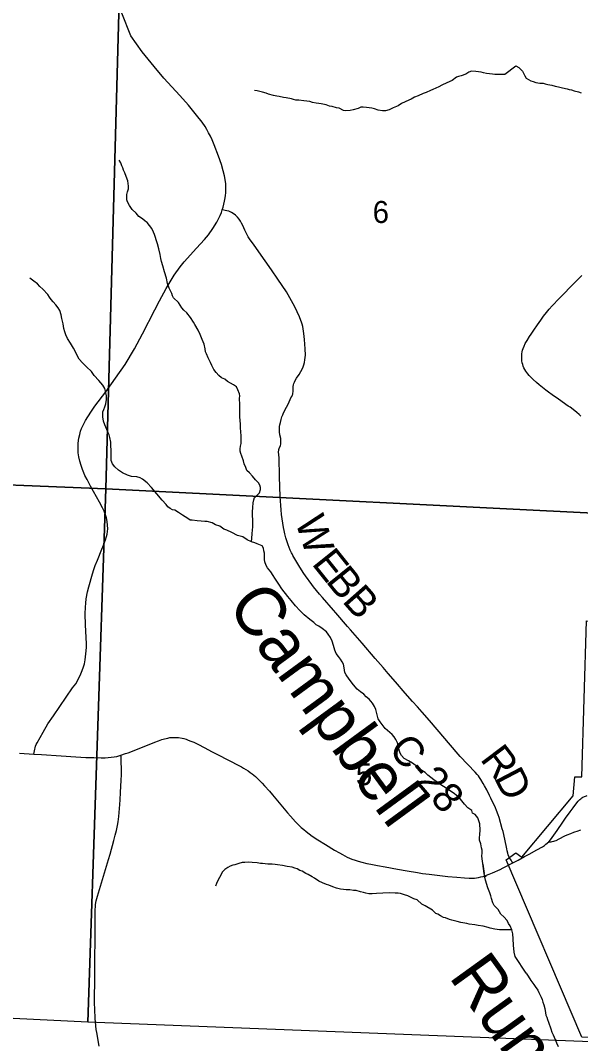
# Model space of a CAD drawing. Extents: x 0 to 34, y 0 to 22.
# Drawn here: x 4.079 to 5.147, y 17.611 to 19.561 of the extents above; entities that cross this region are included whole.
import ezdxf

# ---------------------------------------------------------------- set-up
doc = ezdxf.new("R2010")
doc.units = 0
for name, color, linetype in [('GM_X_City_Street', 7, 'Continuous'), ('GM_X_Corporation', 7, 'Continuous'), ('GM_X_County_Road', 7, 'Continuous'), ('GM_X_County_Road_Text', 7, 'Continuous'), ('GM_X_Minor_River', 7, 'Continuous'), ('GM_X_Minor_River_Text', 7, 'Continuous'), ('GM_X_Section_Text', 7, 'Continuous'), ('GM_X_State_Route', 7, 'Continuous'), ('GM_X_Township_Road', 7, 'Continuous')]:
    doc.layers.add(name, color=color, linetype=linetype)

msp = doc.modelspace()

# ---------------------------------------------------------------- linework, layer by layer
at = {"layer": 'GM_X_City_Street'}
msp.add_lwpolyline([(5.0858, 17.9954), (5.088, 17.9954), (5.0903, 17.9954), (5.0927, 17.9957), (5.0955, 17.9962), (5.0978, 17.9968), (5.0999, 17.9976), (5.1061, 18.0008), (5.1165, 18.0064), (5.1208, 18.0084), (5.128, 18.0113), (5.1338, 18.0136), (5.1418, 18.0162), (5.145, 18.0172), (5.1474, 18.0179)], dxfattribs=at)
at = {"layer": 'GM_X_Corporation'}
for points in [[(3.2518, 19.8039), (4.2724, 19.7849), (4.2417, 18.6679), (3.2101, 18.7098), (3.226, 19.805)], [(4.2853, 19.7839), (5.2933, 19.7705), (5.2887, 19.6211), (5.2602, 18.6174), (4.2417, 18.6679), (4.2724, 19.7849)], [(4.2417, 18.6679), (4.2074, 17.6513), (3.1848, 17.7013), (3.2101, 18.7098)], [(4.2417, 18.6679), (5.2602, 18.6174), (5.2318, 17.611), (4.2074, 17.6513)], [(5.1491, 17.6228), (5.0046, 17.9608), (5.023, 17.9742), (5.0344, 17.9657), (5.1325, 18.083), (5.1358, 18.119), (5.1491, 18.119), (5.158, 18.4166), (5.527, 18.415), (5.5234, 18.0969), (5.4552, 18.0962), (5.4557, 17.9574), (5.3812, 17.9572), (5.3516, 17.6218)]]:
    msp.add_lwpolyline(points, close=True, dxfattribs=at)
at = {"layer": 'GM_X_County_Road'}
for points in [[(4.1424, 18.2356), (4.1787, 18.2889), (4.1846, 18.2966), (4.1884, 18.3031), (4.1945, 18.3154), (4.197, 18.3218), (4.1993, 18.3285), (4.2011, 18.3345), (4.2026, 18.3424), (4.2047, 18.359), (4.2053, 18.3663), (4.2054, 18.3728), (4.2033, 18.4087), (4.2027, 18.4297), (4.2031, 18.4426), (4.2038, 18.4504), (4.2046, 18.4587), (4.207, 18.4717), (4.2094, 18.4815), (4.2164, 18.506), (4.219, 18.5141), (4.2217, 18.522), (4.2258, 18.5319), (4.2344, 18.5528), (4.2377, 18.5608), (4.2413, 18.5706), (4.2433, 18.5774), (4.2443, 18.5819), (4.2451, 18.587), (4.2456, 18.5921), (4.2447, 18.6061), (4.2432, 18.6127), (4.241, 18.6188), (4.2385, 18.6257), (4.2356, 18.6316), (4.2298, 18.6429), (4.2126, 18.6735), (4.2062, 18.6859), (4.2022, 18.6937), (4.1999, 18.6989), (4.1972, 18.7052), (4.1948, 18.7126), (4.1922, 18.7211), (4.1904, 18.7293), (4.1895, 18.737), (4.1891, 18.7481), (4.1893, 18.7543), (4.1899, 18.7601), (4.1907, 18.7649), (4.1922, 18.7715), (4.1939, 18.7779), (4.1958, 18.7829), (4.198, 18.788), (4.2033, 18.7985), (4.2133, 18.8145), (4.2211, 18.8259), (4.242, 18.8531), (4.2789, 18.9052), (4.2968, 18.9349), (4.3115, 18.9639), (4.3353, 19.0093), (4.3444, 19.0263), (4.357, 19.0499), (4.3724, 19.0753), (4.3837, 19.0912), (4.3913, 19.1009), (4.4144, 19.1267), (4.4301, 19.1432), (4.4378, 19.1525), (4.4457, 19.1643), (4.4532, 19.1768), (4.4596, 19.1892), (4.4623, 19.1952), (4.4639, 19.1999), (4.4654, 19.2053), (4.4667, 19.2106), (4.4681, 19.2169), (4.4691, 19.223), (4.4698, 19.2271), (4.4705, 19.2324), (4.4709, 19.237), (4.4706, 19.2498), (4.4696, 19.2579), (4.4681, 19.2652), (4.4655, 19.2747), (4.4623, 19.2864), (4.4568, 19.3026), (4.4481, 19.3243), (4.4445, 19.3334), (4.4411, 19.3406), (4.4378, 19.3471), (4.4344, 19.3534), (4.431, 19.359), (4.4252, 19.3675), (4.4149, 19.3808), (4.3994, 19.3997), (4.3828, 19.4181), (4.3526, 19.4512), (4.3341, 19.4733), (4.311, 19.5012), (4.2897, 19.5316), (4.2723, 19.5751)], [(4.5967, 18.5442), (4.5957, 18.5461), (4.5932, 18.5513), (4.5912, 18.556), (4.5891, 18.5616), (4.5872, 18.567), (4.5849, 18.5748), (4.5829, 18.5826), (4.5815, 18.5886), (4.5804, 18.5944), (4.5777, 18.6112), (4.5768, 18.619), (4.5759, 18.6284), (4.5752, 18.6365), (4.5745, 18.645), (4.5741, 18.653), (4.5731, 18.6919), (4.5721, 18.727), (4.5711, 18.7387), (4.5713, 18.7417), (4.5716, 18.7433), (4.5722, 18.745), (4.5745, 18.7509), (4.5751, 18.7532), (4.5755, 18.7557), (4.5757, 18.7579), (4.5754, 18.7621), (4.5751, 18.7644), (4.5737, 18.7713), (4.5728, 18.7769), (4.5726, 18.7796), (4.573, 18.7871), (4.5734, 18.7901), (4.5745, 18.7949), (4.5759, 18.8002), (4.5774, 18.8051), (4.579, 18.8093), (4.5807, 18.8132), (4.586, 18.8236), (4.5892, 18.8297), (4.5935, 18.8387), (4.5947, 18.8414), (4.5963, 18.8444), (4.5974, 18.8471), (4.598, 18.8486), (4.5983, 18.8502), (4.5987, 18.854), (4.5988, 18.8586), (4.5992, 18.8631), (4.5998, 18.8661), (4.6005, 18.8691), (4.6014, 18.8716), (4.6027, 18.8747), (4.6054, 18.879), (4.6102, 18.8859), (4.6137, 18.8917), (4.6164, 18.8973), (4.6179, 18.9009), (4.6191, 18.9046), (4.6202, 18.9089), (4.6211, 18.9139), (4.6218, 18.9186), (4.6223, 18.9227), (4.622, 18.9353), (4.6203, 18.9531), (4.6191, 18.9644), (4.6171, 18.9776), (4.6163, 18.9818), (4.6156, 18.9839), (4.6111, 18.9962), (4.6024, 19.0151), (4.5865, 19.0435), (4.5699, 19.0677), (4.5576, 19.0859), (4.5333, 19.1201), (4.5231, 19.1343), (4.5168, 19.1427), (4.5132, 19.1487), (4.5071, 19.161), (4.5029, 19.1705), (4.5005, 19.1747), (4.4985, 19.1782), (4.4957, 19.182), (4.4926, 19.1859), (4.4889, 19.1897), (4.4847, 19.1932), (4.4816, 19.1952), (4.479, 19.1964), (4.4761, 19.1973), (4.4728, 19.1981), (4.4639, 19.1999)], [(5.0143, 17.96), (5.0111, 17.9648), (5.0099, 17.9671), (5.0088, 17.9701), (5.0079, 17.9735), (5.007, 17.9778), (5.0061, 17.9819), (5.0024, 18.0001), (4.9989, 18.0147), (4.9973, 18.0202), (4.9912, 18.0418), (4.9897, 18.0466), (4.9864, 18.0549), (4.9843, 18.06), (4.9759, 18.0781), (4.973, 18.0836), (4.9679, 18.0942), (4.9637, 18.102), (4.9612, 18.1065), (4.9564, 18.1142), (4.9541, 18.1176), (4.952, 18.1207), (4.9495, 18.1236), (4.9456, 18.1277), (4.9173, 18.158), (4.9136, 18.1622), (4.8587, 18.2262), (4.845, 18.2421), (4.8357, 18.2522), (4.8262, 18.2628), (4.8124, 18.2788), (4.794, 18.3001), (4.7798, 18.316), (4.7705, 18.3273), (4.7553, 18.3446), (4.7303, 18.3738), (4.708, 18.399), (4.7022, 18.4059), (4.6802, 18.4316), (4.6756, 18.4368), (4.6547, 18.4609), (4.649, 18.4673), (4.6376, 18.4814), (4.6345, 18.4856), (4.6223, 18.5022), (4.6194, 18.5064), (4.6117, 18.5185), (4.6076, 18.5253), (4.5983, 18.5412), (4.5967, 18.5442)], [(4.1047, 18.1625), (4.1058, 18.1685), (4.1064, 18.1718), (4.107, 18.1746), (4.1078, 18.1776), (4.1091, 18.1805), (4.111, 18.184), (4.1223, 18.2039), (4.1317, 18.2198), (4.1424, 18.2356)], [(4.0773, 18.1639), (4.1047, 18.1625)], [(5.0176, 17.9549), (5.0158, 17.9577), (5.0143, 17.96)]]:
    msp.add_lwpolyline(points, dxfattribs=at)
at = {"layer": 'GM_X_Minor_River'}
for points in [[(5.0025, 19.4589), (5.0235, 19.4744), (5.0289, 19.4716), (5.036, 19.4646), (5.0405, 19.4553), (5.043, 19.4509), (5.0476, 19.4484), (5.0519, 19.4463), (5.0561, 19.4449), (5.0611, 19.4428), (5.0691, 19.4416), (5.0752, 19.4414), (5.0794, 19.4404), (5.0844, 19.439), (5.0916, 19.4378), (5.0982, 19.4361), (5.1043, 19.4348), (5.112, 19.4328), (5.1208, 19.4308), (5.125, 19.4295), (5.1292, 19.4288), (5.1342, 19.4267), (5.1426, 19.4248), (5.148, 19.4231)], [(5.0028, 19.4581), (4.9959, 19.4584), (4.9834, 19.4583), (4.9789, 19.459), (4.9732, 19.4593), (4.9671, 19.46), (4.9618, 19.4611), (4.9569, 19.4625), (4.9467, 19.4639), (4.9387, 19.4642), (4.9334, 19.4626), (4.9278, 19.4588), (4.9188, 19.4553), (4.9142, 19.4541), (4.9101, 19.4529), (4.9022, 19.4468), (4.8916, 19.4421), (4.8822, 19.4378), (4.8762, 19.4347), (4.8649, 19.4293), (4.8608, 19.4278), (4.8525, 19.4239), (4.8465, 19.4219), (4.8374, 19.4173), (4.8299, 19.4149), (4.8239, 19.4111), (4.8193, 19.4091), (4.8122, 19.4057), (4.8054, 19.4026), (4.7987, 19.3983), (4.7896, 19.3944), (4.7821, 19.3909), (4.7749, 19.389), (4.7692, 19.3885), (4.7609, 19.39), (4.7541, 19.3925), (4.7487, 19.3936), (4.7389, 19.3954), (4.7321, 19.3961), (4.7279, 19.3956), (4.7226, 19.3933), (4.7132, 19.3909), (4.7075, 19.3897), (4.6992, 19.3889), (4.695, 19.3896), (4.6867, 19.3937), (4.6817, 19.3947), (4.6734, 19.3969), (4.6684, 19.3976), (4.662, 19.4002), (4.6521, 19.402), (4.6476, 19.4027), (4.6426, 19.4034), (4.6358, 19.4048), (4.6309, 19.4063), (4.6195, 19.4081), (4.61, 19.4091), (4.6043, 19.4094), (4.5998, 19.4105), (4.5956, 19.4116), (4.5857, 19.4134), (4.5808, 19.4141), (4.5725, 19.4159), (4.5679, 19.4166), (4.5615, 19.418), (4.552, 19.4209), (4.5474, 19.4224), (4.5402, 19.4242), (4.5353, 19.4257), (4.5303, 19.4267), (4.5254, 19.4274)], [(4.2853, 19.2403), (4.2853, 19.2449), (4.2844, 19.2501), (4.2836, 19.2554), (4.2805, 19.2637), (4.2781, 19.2705), (4.2758, 19.2757), (4.2746, 19.2799), (4.2727, 19.284), (4.2707, 19.2897), (4.2676, 19.2945)], [(4.5196, 18.5672), (4.5206, 18.5815), (4.5216, 18.5905), (4.5223, 18.5947), (4.5221, 18.6097), (4.5216, 18.6168), (4.5216, 18.6244), (4.5218, 18.6326), (4.5225, 18.6417), (4.5239, 18.6473), (4.5254, 18.6515), (4.5295, 18.6553), (4.5347, 18.6606), (4.5369, 18.6667), (4.5365, 18.6708), (4.5357, 18.6749), (4.5326, 18.6798), (4.5273, 18.685), (4.5215, 18.6921), (4.5154, 18.6988), (4.5104, 18.7032), (4.5084, 18.7085), (4.5057, 18.7156), (4.5041, 18.7212), (4.501, 18.7306), (4.4994, 18.7358), (4.4982, 18.74), (4.4982, 18.7441), (4.4985, 18.7494), (4.4996, 18.7543), (4.4999, 18.7614), (4.4998, 18.769), (4.4993, 18.7769), (4.4988, 18.7844), (4.4984, 18.7915), (4.4974, 18.8055), (4.4974, 18.8096), (4.4976, 18.8235), (4.4972, 18.8288), (4.4967, 18.8401), (4.497, 18.8454), (4.4969, 18.8495), (4.4934, 18.857), (4.4907, 18.8626), (4.4854, 18.8663), (4.4797, 18.8693), (4.4736, 18.8726), (4.469, 18.8771), (4.4625, 18.88), (4.4575, 18.8841), (4.4522, 18.8897), (4.4479, 18.8957), (4.4441, 18.9032), (4.4413, 18.9092), (4.4371, 18.9178), (4.4336, 18.9253), (4.432, 18.9294), (4.4312, 18.9351), (4.4292, 18.9437), (4.4253, 18.9527), (4.4214, 18.9625), (4.4179, 18.9704), (4.4113, 18.9816), (4.409, 18.9857), (4.4032, 18.9951), (4.3963, 19.0037), (4.3906, 19.0089), (4.3867, 19.013), (4.3833, 19.0183), (4.3802, 19.0231), (4.371, 19.0321), (4.3687, 19.0362), (4.3675, 19.0403), (4.3628, 19.0505), (4.3597, 19.0599), (4.3573, 19.0697), (4.3538, 19.0817), (4.3506, 19.093), (4.3479, 19.1016), (4.347, 19.1073), (4.3454, 19.1152), (4.3427, 19.1257), (4.3403, 19.1355), (4.3387, 19.1412), (4.3359, 19.1491), (4.3344, 19.1532), (4.3328, 19.1577), (4.3297, 19.1645), (4.3209, 19.1757), (4.3167, 19.1783), (4.3117, 19.1832), (4.3045, 19.1876), (4.2995, 19.1936), (4.2922, 19.2007), (4.2872, 19.2082), (4.2833, 19.215), (4.2821, 19.2191), (4.2817, 19.224), (4.282, 19.2293), (4.2831, 19.2342), (4.2853, 19.2403)], [(4.1467, 19.0191), (4.1417, 19.0247), (4.1379, 19.0292), (4.1348, 19.0337), (4.1313, 19.0386), (4.1217, 19.049), (4.1164, 19.0539), (4.1114, 19.0587), (4.1049, 19.0643), (4.0973, 19.0699)], [(4.643, 18.4086), (4.638, 18.4134), (4.6304, 18.4189), (4.6201, 18.4278), (4.6116, 18.4364), (4.6036, 18.4449), (4.5951, 18.455), (4.589, 18.4628), (4.5774, 18.4777), (4.5717, 18.4866), (4.5663, 18.4937), (4.564, 18.4978), (4.5609, 18.503), (4.5562, 18.5101), (4.5501, 18.5176), (4.5474, 18.522), (4.545, 18.5288), (4.5442, 18.5333), (4.5441, 18.5453), (4.5433, 18.5502), (4.5425, 18.5547), (4.5401, 18.5595), (4.5302, 18.5632), (4.5261, 18.565), (4.5196, 18.5672), (4.5112, 18.5712), (4.5032, 18.5764), (4.4929, 18.5793), (4.4823, 18.5848), (4.4724, 18.5892), (4.4671, 18.5914), (4.459, 18.597), (4.4511, 18.5995), (4.4446, 18.6036), (4.4351, 18.6057), (4.4309, 18.6061), (4.4237, 18.6064), (4.4158, 18.6074), (4.4067, 18.6081), (4.4025, 18.6084), (4.3979, 18.6117), (4.388, 18.618), (4.3804, 18.6228), (4.3735, 18.6272), (4.369, 18.6283), (4.3648, 18.6309), (4.3598, 18.6339), (4.3571, 18.638), (4.3494, 18.6465), (4.3287, 18.6704), (4.3207, 18.6793), (4.3119, 18.6864), (4.3073, 18.689), (4.3008, 18.6908), (4.291, 18.6918), (4.2834, 18.694), (4.2739, 18.6984), (4.2659, 18.7035), (4.259, 18.7099), (4.2544, 18.7158), (4.2524, 18.7222), (4.2519, 18.7346), (4.2522, 18.7391), (4.2517, 18.7527), (4.2512, 18.7572), (4.2496, 18.7658), (4.248, 18.7711), (4.2461, 18.7752), (4.2437, 18.7812), (4.2399, 18.7902), (4.2375, 18.7973), (4.2359, 18.8052), (4.2365, 18.8147), (4.238, 18.8192), (4.2398, 18.8245), (4.242, 18.8302), (4.2431, 18.8385), (4.2434, 18.8456), (4.2414, 18.8543), (4.2402, 18.8595), (4.2359, 18.8655), (4.2283, 18.8745), (4.2198, 18.8842), (4.2148, 18.892), (4.2052, 18.9006), (4.1976, 18.9084), (4.1911, 18.9155), (4.1887, 18.9196), (4.1852, 18.9268), (4.1802, 18.9365), (4.1744, 18.9459), (4.1686, 18.9548), (4.1655, 18.962), (4.1636, 18.9672), (4.162, 18.9736), (4.1607, 18.983), (4.1584, 18.9928), (4.1571, 19), (4.154, 19.0082), (4.1513, 19.0131), (4.1467, 19.0191)], [(4.9603, 17.9526), (4.9629, 17.9346), (4.9583, 17.9676), (4.959, 17.9744), (4.959, 17.9792), (4.9581, 17.9837), (4.9565, 17.9916), (4.9542, 17.998), (4.9541, 18.0025), (4.9548, 18.0089), (4.9551, 18.0171), (4.9546, 18.0295), (4.951, 18.0408), (4.946, 18.0471), (4.9407, 18.0496), (4.9391, 18.0549), (4.9319, 18.0601), (4.9253, 18.0671), (4.9204, 18.0731), (4.9157, 18.079), (4.9062, 18.0864), (4.8921, 18.0964), (4.8787, 18.1053), (4.8669, 18.113), (4.8554, 18.1219), (4.8504, 18.1271), (4.8424, 18.1323), (4.8359, 18.1382), (4.8264, 18.1448), (4.8187, 18.1496), (4.8107, 18.154), (4.8054, 18.1596), (4.8027, 18.1641), (4.8007, 18.1697), (4.8003, 18.175), (4.7975, 18.1836), (4.7948, 18.1899), (4.7917, 18.1951), (4.7878, 18.2), (4.7787, 18.2074), (4.7745, 18.2111), (4.7702, 18.2163), (4.7648, 18.2241), (4.761, 18.2293), (4.759, 18.2372), (4.7566, 18.2473), (4.7539, 18.2529), (4.7504, 18.2592), (4.7439, 18.267), (4.7381, 18.2718), (4.7335, 18.2767), (4.7271, 18.2811), (4.7209, 18.2863), (4.7137, 18.2945), (4.7056, 18.3053), (4.6998, 18.3135), (4.6975, 18.3179), (4.697, 18.3221), (4.6962, 18.3269), (4.6946, 18.334), (4.6923, 18.3385), (4.6892, 18.3434), (4.685, 18.3486), (4.6811, 18.3542), (4.6784, 18.3605), (4.6756, 18.3695), (4.6733, 18.3777), (4.6702, 18.3845), (4.6656, 18.3908), (4.6625, 18.3956), (4.6544, 18.4019), (4.6476, 18.406), (4.643, 18.4086)], [(5.0153, 17.8273), (4.9918, 17.827), (4.9835, 17.8284), (4.9744, 17.8306), (4.9702, 17.8317), (4.9611, 17.8342), (4.9512, 17.8356), (4.9448, 17.837), (4.9345, 17.8384), (4.9296, 17.8391), (4.9224, 17.8409), (4.9182, 17.8412), (4.9114, 17.843), (4.9015, 17.8459), (4.8969, 17.847), (4.8893, 17.8499), (4.8852, 17.851), (4.8798, 17.8543), (4.8749, 17.8569), (4.8707, 17.8587), (4.8642, 17.865), (4.8504, 17.8732), (4.844, 17.8765), (4.8355, 17.8843), (4.8287, 17.8864), (4.8177, 17.892), (4.8108, 17.8938), (4.8032, 17.8963), (4.7987, 17.897), (4.793, 17.8973), (4.782, 17.8979), (4.7699, 17.8974), (4.7578, 17.8965), (4.7495, 17.8961), (4.7434, 17.896), (4.7374, 17.897), (4.7328, 17.8985), (4.7275, 17.8996), (4.7191, 17.9021), (4.7138, 17.9024), (4.707, 17.9035), (4.6998, 17.9038), (4.6949, 17.9045), (4.6892, 17.9051), (4.6812, 17.9066), (4.6748, 17.9091), (4.6671, 17.9124), (4.6626, 17.9139), (4.655, 17.9168), (4.6477, 17.9204), (4.6393, 17.926), (4.6352, 17.9282), (4.6275, 17.933), (4.623, 17.9348), (4.6161, 17.9392), (4.6119, 17.9407), (4.6066, 17.9436), (4.6024, 17.9447), (4.5967, 17.9465), (4.5872, 17.9483), (4.5789, 17.9501), (4.569, 17.9515), (4.5648, 17.9518), (4.5588, 17.9525), (4.5504, 17.9528), (4.5406, 17.9538), (4.5364, 17.9541), (4.5304, 17.9548), (4.5205, 17.9558), (4.5137, 17.9561), (4.5065, 17.956), (4.5016, 17.9556), (4.4955, 17.954), (4.488, 17.9513), (4.4839, 17.9505), (4.4786, 17.9486), (4.4741, 17.9463), (4.4688, 17.9424), (4.4636, 17.9371), (4.4617, 17.9326), (4.4584, 17.9269), (4.4554, 17.9216), (4.4528, 17.9159), (4.4506, 17.9107)], [(5.0432, 17.7449), (5.0219, 17.7762), (5.0199, 17.7845), (5.0186, 17.7984), (5.0181, 17.8104), (5.0173, 17.8198), (5.0153, 17.8273), (5.0122, 17.8351), (5.0095, 17.8396), (5.0064, 17.8452), (5.0006, 17.8519), (4.9945, 17.8575), (4.9898, 17.8661), (4.9822, 17.8739), (4.9791, 17.8788), (4.9767, 17.887), (4.9759, 17.8919), (4.9736, 17.8979), (4.97, 17.9072), (4.9653, 17.9222), (4.9641, 17.9278), (4.9629, 17.9346), (4.9629, 17.9351)], [(4.9656, 17.9297), (4.966, 17.9286)], [(5.0432, 17.7449), (5.0468, 17.739), (5.0521, 17.7309), (5.0573, 17.7232), (5.0601, 17.7192), (5.0649, 17.7122), (5.0673, 17.7077), (5.0715, 17.6988), (5.0731, 17.6944), (5.0748, 17.6895), (5.0765, 17.6843), (5.0783, 17.6772), (5.0798, 17.669), (5.0807, 17.6649), (5.082, 17.6608), (5.0836, 17.6563), (5.0854, 17.6511), (5.09, 17.6388), (5.0921, 17.6321), (5.0942, 17.6269), (5.0963, 17.6224), (5.0979, 17.6184), (5.1008, 17.6117), (5.1041, 17.6046)]]:
    msp.add_lwpolyline(points, dxfattribs=at)
at = {"layer": 'GM_X_State_Route'}
for points in [[(5.1472, 18.8066), (5.1438, 18.8101), (5.1396, 18.8138), (5.1357, 18.8169), (5.1265, 18.8237), (5.1232, 18.826), (5.1046, 18.8388), (5.0922, 18.8476), (5.0855, 18.8523), (5.0805, 18.8562), (5.0678, 18.8664), (5.0624, 18.871), (5.0565, 18.8763), (5.0528, 18.8798), (5.0489, 18.8839), (5.0462, 18.8871), (5.0426, 18.8922), (5.0404, 18.8955), (5.0386, 18.8991), (5.0374, 18.9023), (5.0363, 18.9053), (5.0355, 18.9083), (5.0349, 18.912), (5.0346, 18.9152), (5.0344, 18.9189), (5.0347, 18.9258), (5.0353, 18.9291), (5.0361, 18.9322), (5.0372, 18.9357), (5.0388, 18.9402), (5.0412, 18.9452), (5.0446, 18.951), (5.0493, 18.9586), (5.0522, 18.9629), (5.0573, 18.9707), (5.0645, 18.9808), (5.0707, 18.9899), (5.0762, 18.9972), (5.0818, 19.0045), (5.0868, 19.0107), (5.0926, 19.0171), (5.1056, 19.0311), (5.1125, 19.0379), (5.1294, 19.0551), (5.1404, 19.0661), (5.1492, 19.0747)], [(4.1047, 18.1625), (4.1195, 18.1616), (4.1566, 18.1592), (4.1849, 18.1572), (4.204, 18.1562), (4.2191, 18.1556), (4.233, 18.1554), (4.2405, 18.1554), (4.2461, 18.1557), (4.2522, 18.1563), (4.2575, 18.157), (4.2626, 18.158), (4.2664, 18.1591), (4.2707, 18.1605), (4.2797, 18.1633), (4.2846, 18.1651), (4.3118, 18.1758), (4.3352, 18.1853), (4.3422, 18.1879), (4.3488, 18.1902), (4.3536, 18.1916), (4.3599, 18.193), (4.3641, 18.1937), (4.3702, 18.1942), (4.3786, 18.1939), (4.3807, 18.1937), (4.3872, 18.1926), (4.3908, 18.1918), (4.3947, 18.1907), (4.3991, 18.1892), (4.4041, 18.1873), (4.4095, 18.1849), (4.4174, 18.181), (4.4309, 18.174), (4.4431, 18.1676), (4.4584, 18.1596), (4.4716, 18.1528), (4.5004, 18.1378), (4.5042, 18.1356), (4.5131, 18.1302), (4.517, 18.1274), (4.5205, 18.1249), (4.5272, 18.1195), (4.5319, 18.115), (4.5397, 18.1071), (4.5446, 18.1018), (4.5537, 18.0915), (4.5595, 18.0848), (4.5662, 18.0768), (4.5755, 18.0656), (4.5881, 18.0504), (4.5937, 18.0438), (4.6034, 18.0332), (4.6076, 18.0289), (4.6143, 18.0225), (4.619, 18.0183), (4.6236, 18.0145), (4.6291, 18.0102), (4.6354, 18.0058), (4.6461, 17.9989), (4.6605, 17.9899), (4.6779, 17.9795), (4.687, 17.9742), (4.6928, 17.9708), (4.7019, 17.966), (4.706, 17.9642), (4.7108, 17.9622), (4.7169, 17.96), (4.7228, 17.9581), (4.7298, 17.9562), (4.7391, 17.954), (4.7469, 17.9524), (4.7599, 17.95), (4.7741, 17.9473), (4.7976, 17.9431), (4.8163, 17.9396), (4.8357, 17.9365), (4.8452, 17.9349), (4.8583, 17.9332), (4.8939, 17.9292), (4.9106, 17.9275), (4.9257, 17.9263), (4.9341, 17.9259), (4.9443, 17.9261), (4.9482, 17.9264), (4.9523, 17.9271), (4.9568, 17.9281), (4.9608, 17.9293), (4.9726, 17.9334), (4.9788, 17.936), (4.9934, 17.9426), (4.9994, 17.9455), (5.0176, 17.9549)], [(4.0773, 18.1639), (4.1047, 18.1625)], [(5.1449, 18.0756), (5.1468, 18.0772), (5.1488, 18.0788), (5.1507, 18.08), (5.1538, 18.0816), (5.1561, 18.0824), (5.1581, 18.083), (5.1594, 18.0833)], [(5.1193, 18.0419), (5.1198, 18.0426), (5.1268, 18.0522), (5.1327, 18.06), (5.1394, 18.0693), (5.1422, 18.0729), (5.1449, 18.0756)], [(5.0858, 17.9954), (5.0891, 17.9991), (5.1017, 18.017), (5.1128, 18.0327), (5.1193, 18.0419)], [(5.0176, 17.9549), (5.0274, 17.9602), (5.04, 17.967), (5.0487, 17.9717), (5.0633, 17.9796), (5.074, 17.9855), (5.0779, 17.9882), (5.0807, 17.9904), (5.0858, 17.9954)]]:
    msp.add_lwpolyline(points, dxfattribs=at)
at = {"layer": 'GM_X_Township_Road'}
msp.add_lwpolyline([(4.229, 17.6053), (4.2246, 17.6315), (4.2238, 17.6375), (4.2224, 17.6517), (4.2219, 17.6578), (4.2208, 17.6767), (4.2206, 17.6871), (4.2205, 17.6993), (4.2207, 17.7284), (4.2215, 17.853), (4.2216, 17.8559), (4.2219, 17.8661), (4.2222, 17.8709), (4.2225, 17.8753), (4.2235, 17.8824), (4.2261, 17.8918), (4.2471, 17.9617), (4.2501, 17.9717), (4.2573, 17.9976), (4.2597, 18.0077), (4.2621, 18.017), (4.2639, 18.026), (4.2655, 18.0334), (4.2668, 18.0433), (4.2684, 18.0662), (4.2691, 18.0753), (4.2701, 18.0893), (4.2708, 18.1012), (4.2713, 18.1123), (4.2715, 18.1234), (4.2717, 18.133), (4.2714, 18.1487), (4.271, 18.1573), (4.2708, 18.1592), (4.2707, 18.1605)], dxfattribs=at)

# ---------------------------------------------------------------- texts
at = {"layer": 'GM_X_County_Road_Text'}
for s, height, rotation, p in [('W', 0.0568, 288.1611, (4.6021, 18.6068)), ('E', 0.0568, 308.6499, (4.6329, 18.5252)), ('B', 0.0568, 308.8803, (4.6596, 18.4918)), ('B', 0.0568, 311.5127, (4.6907, 18.4534)), ('C-28', 0.05682, 310.5702, (4.7786, 18.1705)), ('R', 0.0568, 307.1236, (4.9539, 18.1525)), ('D', 0.0568, 297.6493, (4.9807, 18.1174))]:
    msp.add_text(s, height=height, rotation=rotation, dxfattribs=at).set_placement(p)
at = {"layer": 'GM_X_Minor_River_Text'}
for s, height, rotation, p in [('Campbell', 0.09405, 306.2007, (4.4711, 18.445)), ('Run', 0.09423, 305.8203, (4.8941, 17.738))]:
    msp.add_text(s, height=height, rotation=rotation, dxfattribs=at).set_placement(p)
at = {"layer": 'GM_X_Section_Text'}
for s, p in [('6', (4.7504, 19.175)), ('5', (4.7183, 18.103))]:
    msp.add_text(s, height=0.0419, rotation=0, dxfattribs=at).set_placement(p)

doc.saveas('drawing.dxf')
